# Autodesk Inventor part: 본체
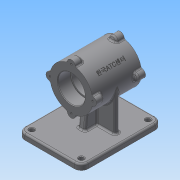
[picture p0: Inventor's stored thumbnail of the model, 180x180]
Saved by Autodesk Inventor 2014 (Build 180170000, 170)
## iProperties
Created: 2015-12
Part Number: 본체
Material: 일반
Document SubType Name: Modeling
Designer: net
Density: 1 g/cm^3
Appearance: 기본값
Author: net
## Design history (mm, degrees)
sketch "스케치4"
  geometry: L1 (-42.5, 0)-(42.5, 0); L2 (42.5, 0)-(42.5, 37); L3 (-26.809, 37)-(-42.5, 37); L4 (-42.5, 37)-(-42.5, 0); L5 (26.809, 37)-(42.5, 37); L6 (-26.809, 37)-(26.809, 37); L7 (-42.5, 23.5)-(-20.8, 23.5); L8 (-20.5, 23.2)-(-20.5, 0); L9 (42.5, 23.5)-(20.8, 23.5); L10 (20.5, 23.2)-(20.5, 0); L11 (20.5, 21)-(-20.5, 21); A1 r 0.3 centre (-20.8, 23.2) between (-20.5, 23.2) and (-20.8, 23.5); A2 r 0.3 centre (20.8, 23.2) between (20.8, 23.5) and (20.5, 23.2); 3 further points
  constraints: 22 end point, 6 horizontal, 6 point on line, 4 point on circle, 4 tangent, 4 vertical, 2 centre point, 2 midpoint, 1 coincident, 1 equal radius, 1 vertical alignment
  dimensions: "d19" = 85 distance between parallel lines of L2 L4; "d20" = 74 diameter of L3 L1; "d21" = 74 diameter of L5 L1; "d22" = 42 diameter of L11 L1; "d23" = 47 diameter of L7 L1; "d24" = 47 diameter of L9 L1; "d25" = 22 distance between parallel lines of L2 L10; "d26" = 22 distance between parallel lines of L4 L8; "d27" = 0.3 radius of A1
revolve "회전1" stored, may be unused: angle "d28" = 90 deg
revolve "회전2" stored, may be unused: angle "d29" = 90 deg
sketch "스케치6"
  geometry: L1 (-42.5, 37)-(42.5, 37) reference; L2 (-42.5, -37)-(-42.5, 37) reference; L3 (42.5, -37)-(42.5, 37) reference; L4 (-42.5, 37)-(42.5, 37); L5 (-42.5, 37)-(-42.5, 44); L6 (-42.5, 44)-(-30.048, 44); L7 (-30.048, 44)-(-27.5, 37); L8 (42.5, 37)-(42.5, 44); L9 (42.5, 44)-(30.048, 44); L10 (30.048, 44)-(27.5, 37); 1 further point
  constraints: 14 end point, 3 horizontal, 2 point on line, 2 vertical
  dimensions: "d32" = 14 diameter of L6 L1; "d33" = 14 diameter of L9 L1; "d34" = 110 deg angle of L1 L10; "d35" = 110 deg angle of L1 L7; "d36" = 15 distance from line of L10.end L8; "d37" = 15 distance from line of L5 L7.end
revolve "회전3" sketch "스케치6" stored, may be unused: angle "d38" = 90 deg
fillet "모깎기3" dims "d39" = 3
fillet "모깎기5" dims "d44" = 3
fillet "모깎기6" dims "d45" = 3
fillet "모깎기7" dims "d46" = 3
hole "구멍2" diameter "d49" = 3.242; stored, may be unused: countersink angle "d53" = 90 deg, drill point angle "d55" = 118 deg; dims "d47" = 10, "d48" = 10, "d50" = 9, "d51" = 4, "d52" = 2, "d54" = 11
chamfer "모따기1" distance "d59" = 1; stored, may be unused: second distance "d60" = 2, angle "d61" = 45 deg
chamfer "모따기2" distance "d62" = 1; stored, may be unused: second distance "d63" = 2, angle "d64" = 45 deg
node "작업 평면1"
sketch "스케치8"
  geometry: L1 (-55, -80)-(55, -80); L2 (55, -80)-(55, 60); L3 (55, 60)-(-55, 60); L4 (-55, 60)-(-55, -80); 1 further point
  constraints: 8 end point, 2 horizontal, 1 perpendicular, 1 vertical
  dimensions: "d66" = 110 distance of L1.start L1.end; "d67" = 140 distance of L1.end L2.end; "d68" = 80 distance from line of L1 point (0, 0); "d69" = 55 distance from line of point (0, 0) L4
extrude "돌출3" join sketch "스케치8" distance "d70" = 10; taper "d71" = 0 deg
fillet "모깎기8" dims "d72" = 12
fillet "모깎기9" dims "d73" = 3
sketch "스케치9"
  geometry: A1 r 9 centre (43, -68) between (43, -77) and (52, -68) reference; A2 r 9 centre (43, 48) between (52, 48) and (43, 57) reference; A3 r 9 centre (-43, 48) between (-43, 57) and (-52, 48) reference; A4 r 9 centre (-43, -68) between (-52, -68) and (-43, -77) reference; 1 further point
hole "구멍3" sketch "스케치9" at (-43, -68), (43, -68), (43, 48), (-43, 48) diameter "d77" = 8; stored, may be unused: countersink angle "d81" = 90 deg, drill point angle "d83" = 0 deg; dims "d78" = 9, "d79" = 4, "d80" = 2, "d82" = 30
chamfer "모따기3" distance "d84" = 1; stored, may be unused: second distance "d85" = 2, angle "d86" = 45 deg
chamfer "모따기4" distance "d87" = 1; stored, may be unused: second distance "d88" = 2, angle "d89" = 45 deg
sketch "스케치10"
  geometry: L1 (-37, -4)-(-37, 4); L2 (37, 4)-(37, -4); L3 (-6, 25)-(6, 25); L4 (6, -25)-(-6, -25); L5 (-6, -25)-(-6, -4); L6 (-6, 4)-(-6, 25); L7 (-37, 4)-(-6, 4); L8 (6, 4)-(37, 4); L9 (6, 25)-(6, 4); L10 (6, -4)-(6, -25); L11 (37, -4)-(6, -4); L12 (-6, -4)-(-37, -4); L13 (6, 4)-(-6, 4); L14 (-6, -4)-(6, -4); 9 further points
  constraints: 28 end point, 7 horizontal, 5 vertical, 4 horizontal alignment, 4 midpoint, 4 perpendicular, 4 vertical alignment
  dimensions: "d96" = 74 distance of L2.end L1.start; "d97" = 8 distance of L1.start L1.end; "d98" = 50 distance between parallel lines of L4 L3; "d99" = 12 distance of L4.start L4.end
sketch "스케치11"
  geometry: L1 (0, 0)-(-32.349, 32.349); L2 (0, 0)-(-68.523, 0); A1 r 37 centre (0, 0) between (-9.104, 35.863) and (-35.863, 9.104) reference; 1 further point
  constraints: 4 end point, 1 horizontal
  dimensions: "d106" = 45 deg angle of L2 L1
extrude "돌출6" join sketch "스케치10" stored distance "d113" = 10; taper "d114" = 0 deg
sketch "스케치13"
  geometry: L1 (48, -70)-(-68, -70) reference; L2 (-25, -70)-(-20.948, -37); L3 (20.948, -37)-(25, -70); L4 (-68, -70)-(48, -70) reference; L5 (0, -70)-(0, -37); L6 (0, -70)-(-25, -70); L7 (25, -70)-(0, -70); L8 (-20.948, -37)-(-19.876, -28.27); L9 (20.948, -37)-(19.876, -28.27); L10 (19.876, -28.27)-(-19.876, -28.27); 1 further point
  constraints: 16 end point, 3 horizontal, 3 point on line, 2 collinear, 1 vertical
  dimensions: "d115" = 25 horizontal distance of point (0, 0) L2.start; "d116" = 25 horizontal distance of point (0, 0) L3.end; "d117" = 97 deg angle of L1 L3; "d118" = 97 deg angle of L1 L2
extrude "돌출7" join sketch "스케치13" stored distance "d119" = 12; taper "d120" = 0 deg
node "작업 평면3"
sketch "스케치14"
  geometry: L1 (-42.5, -18.921)-(-42.5, 18.921) reference; 2 further points
  constraints: 1 coincident, 1 other
  dimensions: "d121" = 42.5 distance from line of L1 point (0, 0) (derived)
feature "엠보싱2" sketch "스케치14" dims "d19" = 85, "d20" = 74, "d21" = 74, "d22" = 42, "d23" = 47, "d24" = 47, "d25" = 22, "d26" = 22, "d27" = 0.3, "d29" = 90 deg, "d122" = 0.5, "d123" = 0
fillet "모깎기14" dims "d132" = 3
fillet "모깎기17" dims "d135" = 3
fillet "모깎기18" dims "d136" = 3
fillet "모깎기19" dims "d137" = 3
fillet "모깎기20" dims "d138" = 3
fillet "모깎기21" dims "d139" = 3
node "솔리드2"
pattern_circular "원형 패턴1" dims angle "d42" = 360 deg
pattern_circular "원형 패턴2" dims angle "d57" = 360 deg
mirror "대칭1"
